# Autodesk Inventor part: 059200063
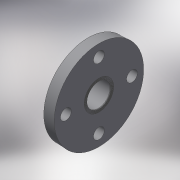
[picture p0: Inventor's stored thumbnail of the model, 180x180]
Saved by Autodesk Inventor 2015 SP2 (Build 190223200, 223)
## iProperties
Created: 2017-10
Part Number: 059200063
Material: Generic
Description: PLASSON FIXED FLANGE-CEM PVC 63
Document SubType Name: Modeling
Designer: KIM
Mass: 335.519 g
Surface Area: 609.224 cm^2
Volume: 335.519 cm^3
Density: 1 g/cm^3
Appearance: Default
Author: KIM
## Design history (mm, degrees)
derived "059200.ipt"
feature "Solid1::059200.ipt"
tag "TaggingFeature1"
body "Solid1"
other parameters: "d0" = 39, "d2" = 165, "d3" = 163.35, "d14" = 18, "d15" = 62.5, "d16" = 39, "d17" = 0, "d19" = 360 deg, "d21" = 38, "d22" = 63, "d23" = 59.85, "d24" = 75.6, "d25" = 0.63, "d26" = 0.825, "d27" = 0.825, "d28" = 0.825, "d29" = 0.825, "d30" = 0.825, "d31" = 0.825, "d32" = 0.33, "d33" = 0, "d34" = 18, "E_" = 165, "H_" = 39, "Dp_" = 125, "S_" = 18, "l_" = 38, "d_" = 63, "H_1" = 18
